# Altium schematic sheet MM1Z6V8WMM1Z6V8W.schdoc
size 127 x 101 mm
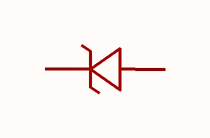
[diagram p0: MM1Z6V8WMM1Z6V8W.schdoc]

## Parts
D?  mm1z6v8w  [SOD-123W_L2.7-W1.8-LS3.7-RD]  (value not drawn)

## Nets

Not connected (* = marked no-connect by the designer): D? 1(C) 2(A)

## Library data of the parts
D? = mm1z6v8w: 二极管配置:1个独立式;稳压值(标称值):6.8V;稳压值(范围值):6.4V~7.2V;耗散功率(Pd):500mW;; Manufacturer: JSMSEMI(杰盛微); AddInBom: yes; ModelId: 4e086b2d10414cc9b14054a09b3635c7; ModelTransform: 145.669,62.992,0,0,0,0,-0.001,0.002,0; Diode Configuration: 1个独立式; Zener Voltage(Nom): 6.8V; Reverse Leakage Current (Ir): 500nA@3.5V; Pd - Power Dissipation: 500mW; Impedance(Zzt): 30Ω; Operating Junction Temperature Range: -55℃~+150℃; Tolerance: ±5%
